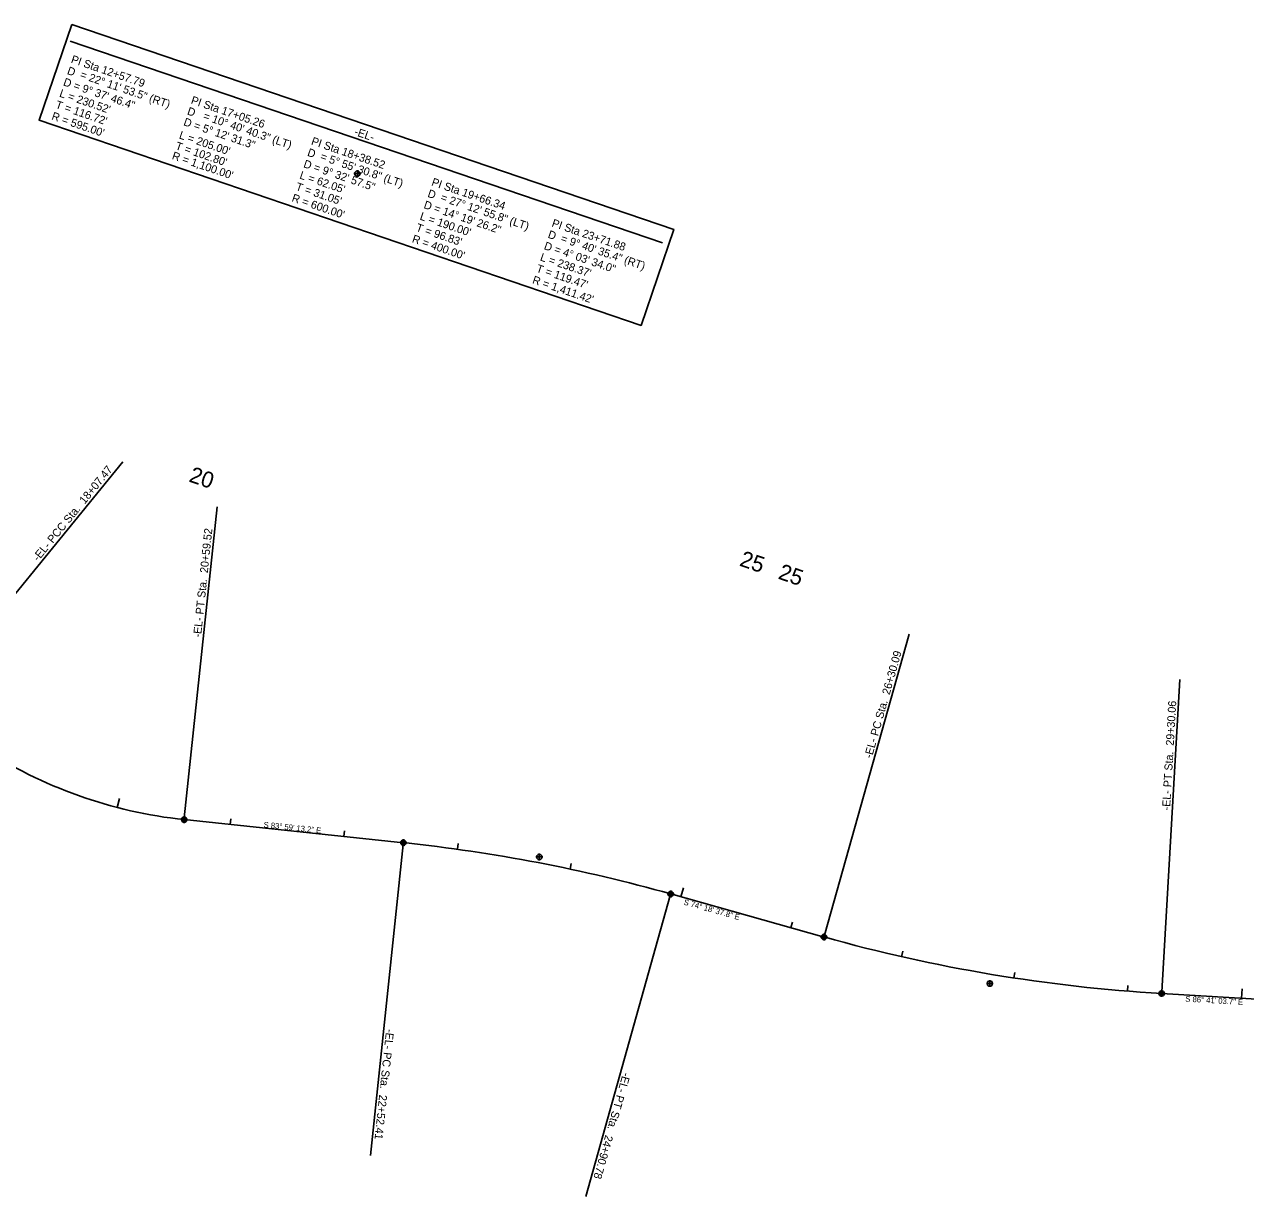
# Model space of a CAD drawing. Extents: x 928071 to 937324, y 684061 to 686812.
# Drawn here: x 928766 to 929834, y 685582 to 686607 of the extents above; entities that cross this region are included whole.
import ezdxf

# ---------------------------------------------------------------- set-up
doc = ezdxf.new("R2010")
doc.units = 0
for name, color, linetype in [('COGO Default Chain', 7, 'Continuous'), ('COGO Default Curve', 7, 'Continuous'), ('Cogo Default Point CELL', 7, 'Continuous'), ('Default', 7, 'Continuous'), ('Exist Horizontal Alignment', 7, 'Continuous'), ('Exist Horizontal Alignment Curve and Spiral Data', 7, 'Continuous'), ('Exist Horizontal Alignment Direction Label', 7, 'Continuous'), ('Exist Horizontal Alignment Station Label', 7, 'Continuous'), ('Exist Horizontal Alignment Tick Label', 7, 'Continuous'), ('Exist Horizontal Alignment Tick Large', 7, 'Continuous'), ('Exist Horizontal Alignment Tick Small', 7, 'Continuous')]:
    doc.layers.add(name, color=color, linetype=linetype)

msp = doc.modelspace()

# ---------------------------------------------------------------- linework, layer by layer
at = {"layer": 'COGO Default Chain'}
for p, q in [((928906, 685911.7), (929097.8, 685891.5)), ((929331.6, 685846.7), (929465.7, 685809)), ((929761, 685759.6), (929854.3, 685754.2))]:
    msp.add_line(p, q, dxfattribs=at)
for centre, radius, start, end in [((928947.9, 686309.5), 400, 236.7715, 263.987), ((928949.9, 684487.9), 1411.4, 74.3105, 83.987), ((929841.4, 687146.3), 1389, 254.3105, 266.6844)]:
    msp.add_arc(centre, radius, start, end, dxfattribs=at)
at = {"layer": 'COGO Default Curve'}
for centre, radius, start, end in [((928947.9, 686309.5), 400, 236.7715, 263.987), ((928949.9, 684487.9), 1411.4, 74.3105, 83.987), ((929841.4, 687146.3), 1389, 254.3105, 266.6844)]:
    msp.add_arc(centre, radius, start, end, dxfattribs=at)
at = {"layer": 'Cogo Default Point CELL'}
for points in [[(929054.5, 686476.8), (929057.5, 686476.8)], [(929057.5, 686479.8), (929057.5, 686476.8)], [(929057.5, 686476.8), (929060.5, 686476.8)], [(929057.5, 686476.8), (929057.5, 686473.8)], [(928903, 685911.7), (928906, 685911.7)], [(928906, 685914.7), (928906, 685911.7)], [(928906, 685911.7), (928909, 685911.7)], [(928906, 685911.7), (928906, 685908.7)], [(929094.8, 685891.5), (929097.8, 685891.5)], [(929097.8, 685894.5), (929097.8, 685891.5)], [(929097.8, 685891.5), (929100.8, 685891.5)], [(929097.8, 685891.5), (929097.8, 685888.5)], [(929213.6, 685879), (929216.6, 685879)], [(929216.6, 685882), (929216.6, 685879)], [(929216.6, 685879), (929219.6, 685879)], [(929216.6, 685879), (929216.6, 685876)], [(929328.6, 685846.7), (929331.6, 685846.7)], [(929331.6, 685849.7), (929331.6, 685846.7)], [(929331.6, 685846.7), (929334.6, 685846.7)], [(929331.6, 685846.7), (929331.6, 685843.7)], [(929462.7, 685809), (929465.7, 685809)], [(929465.7, 685812), (929465.7, 685809)], [(929465.7, 685809), (929468.7, 685809)], [(929465.7, 685809), (929465.7, 685806)], [(929607.7, 685768.3), (929610.7, 685768.3)], [(929610.7, 685771.3), (929610.7, 685768.3)], [(929610.7, 685768.3), (929613.7, 685768.3)], [(929610.7, 685768.3), (929610.7, 685765.3)], [(929761, 685762.6), (929761, 685759.6)], [(929758, 685759.6), (929761, 685759.6)], [(929761, 685759.6), (929764, 685759.6)], [(929761, 685759.6), (929761, 685756.6)]]:
    msp.add_lwpolyline(points, dxfattribs=at)
for centre in [(929057.5, 686476.8), (928906, 685911.7), (929097.8, 685891.5), (929216.6, 685879), (929331.6, 685846.7), (929465.7, 685809), (929610.7, 685768.3), (929761, 685759.6)]:
    msp.add_circle(centre, 2.34, dxfattribs=at)
at = {"layer": 'Default'}
for p, q in [((928906, 685911.7), (929097.8, 685891.5)), ((929465.7, 685809), (929331.6, 685846.7)), ((929854.3, 685754.2), (929761, 685759.6))]:
    msp.add_line(p, q, dxfattribs=at)
msp.add_lwpolyline([(928807.7, 686607.3), (929334.2, 686427.9), (929305.6, 686344), (928779.1, 686523.4)], close=True, dxfattribs=at)
for centre, radius, start, end in [((928947.9, 686309.5), 400, 236.7715, 263.987), ((928949.9, 684487.9), 1411.4, 74.3105, 83.987), ((929841.4, 687146.3), 1389, 254.3105, 266.6844)]:
    msp.add_arc(centre, radius, start, end, dxfattribs=at)
at = {"layer": 'Exist Horizontal Alignment'}
for p, q in [((928906, 685911.7), (929097.8, 685891.5)), ((929331.6, 685846.7), (929465.7, 685809)), ((929761, 685759.6), (929854.3, 685754.2))]:
    msp.add_line(p, q, dxfattribs=at)
for centre, radius, start, end in [((928947.9, 686309.5), 400, 236.7715, 263.987), ((928949.9, 684487.9), 1411.4, 74.3105, 83.987), ((929841.4, 687146.3), 1389, 254.3105, 266.6844)]:
    msp.add_arc(centre, radius, start, end, dxfattribs=at)
at = {"layer": 'Exist Horizontal Alignment Curve and Spiral Data'}
msp.add_line((928806.3, 686592.6), (929324.4, 686416.1), dxfattribs=at)
at = {"layer": 'Exist Horizontal Alignment Station Label'}
for p, q in [((928679.6, 686012.7), (928852.3, 686224.8)), ((928906.1, 685913.2), (928934.8, 686185.2)), ((929466.1, 685810.5), (929540.1, 686073.8)), ((929761.1, 685761.1), (929776.9, 686034.2)), ((929097.6, 685890), (929069, 685618)), ((929331.2, 685845.3), (929257.3, 685582))]:
    msp.add_line(p, q, dxfattribs=at)
for centre in [(928906, 685911.7), (929097.8, 685891.5), (929331.6, 685846.7), (929465.7, 685809), (929761, 685759.6)]:
    msp.add_circle(centre, 1.5, dxfattribs=at)
at = {"layer": 'Exist Horizontal Alignment Tick Large'}
for p, q in [((928847.5, 685922.3), (928849.5, 685930.1)), ((929340.5, 685844.2), (929342.7, 685851.9)), ((929830.8, 685755.6), (929831.3, 685763.6))]:
    msp.add_line(p, q, dxfattribs=at)
at = {"layer": 'Exist Horizontal Alignment Tick Small'}
for p, q in [((928946.2, 685907.5), (928946.7, 685912.5)), ((929045.7, 685897), (929046.2, 685902)), ((929145, 685885.8), (929145.7, 685890.7)), ((929243.5, 685868.4), (929244.5, 685873.3)), ((929436.8, 685817.2), (929438.1, 685822)), ((929533.5, 685791.8), (929534.6, 685796.7)), ((929631.7, 685773.2), (929632.5, 685778.1)), ((929731, 685761.7), (929731.4, 685766.7))]:
    msp.add_line(p, q, dxfattribs=at)

# ---------------------------------------------------------------- texts
at = {"layer": 'Exist Horizontal Alignment Curve and Spiral Data'}
for s, rotation, p in [('PI Sta 12+57.79', 341.0779, (928806.5, 686574)), ('D', 341.0779, (928803.1, 686564)), ('= 22%%d 11\' 53.5" (RT)', 341.0779, (928814.4, 686560.6)), ('D = 9%%d 37\' 46.4"', 341.0779, (928799.7, 686554.1)), ("T = 116.72'", 341.0779, (928792.9, 686534.3)), ("L = 230.52'", 341.0779, (928796.3, 686544.2)), ('PI Sta 17+05.26', 341.1836, (928911.4, 686538.2)), ("R = 595.00'", 341.0779, (928789.5, 686524.3)), ('D', 341.1836, (928908.1, 686528.6)), ('D = 5%%d 12\' 31.3"', 341.1836, (928904.9, 686519.2)), ('= 10%%d 40\' 40.3" (LT)', 341.1836, (928922.1, 686524.4)), ("L = 205.00'", 341.1836, (928901, 686507.7)), ('PI Sta 18+38.52', 341.1836, (929016.6, 686502.4)), ('-EL-', 341.1836, (929054.2, 686510.7)), ("T = 102.80'", 341.1836, (928897.8, 686498.2)), ('D', 341.1836, (929013.2, 686492.5)), ("R = 1,100.00'", 341.1836, (928894.8, 686489.6)), ('D = 9%%d 32\' 57.5"', 341.1836, (929009.8, 686482.5)), ('= 5%%d 55\' 30.8" (LT)', 341.1836, (929024.5, 686489)), ("L = 62.05'", 341.1836, (929006.4, 686472.6)), ("T = 31.05'", 341.1836, (929003, 686462.6)), ('PI Sta 19+66.34', 341.1836, (929121.8, 686466.6)), ("R = 600.00'", 341.1836, (928999.6, 686452.7)), ('D', 341.1836, (929118.4, 686456.6)), ('= 27%%d 12\' 55.8" (LT)', 341.1836, (929129.7, 686453.2)), ('D = 14%%d 19\' 26.2"', 341.1836, (929115, 686446.7)), ("L = 190.00'", 341.1836, (929111.6, 686436.7)), ('PI Sta 23+71.88', 341.1836, (929227, 686430.7)), ("R = 400.00'", 341.1836, (929104.8, 686416.9)), ("T = 96.83'", 341.1836, (929108.2, 686426.8)), ('D', 341.1836, (929223.6, 686420.8)), ('D = 4%%d 03\' 34.0"', 341.1836, (929220.2, 686410.8)), ('= 9%%d 40\' 35.4" (RT)', 341.1836, (929234.8, 686417.3)), ("L = 238.37'", 341.1836, (929216.8, 686400.9)), ("T = 119.47'", 341.1836, (929213.4, 686391)), ("R = 1,411.42'", 341.1836, (929210, 686381))]:
    msp.add_text(s, height=7, rotation=rotation, dxfattribs=at).set_placement(p)
at = {"layer": 'Exist Horizontal Alignment Direction Label'}
for s, rotation, p in [('S 83%%d 59\' 13.2" E', 353.987, (928975.3, 685904.9)), ('S 74%%d 18\' 37.8" E', 344.3105, (929342.5, 685837.4)), ('S 86%%d 41\' 03.7" E', 356.6844, (929781.6, 685752.5))]:
    msp.add_text(s, height=5, rotation=rotation, dxfattribs=at).set_placement(p)
at = {"layer": 'Exist Horizontal Alignment Station Label'}
for s, rotation, p in [('-EL- PCC Sta.  18+07.47', 50.8463, (928778.3, 686137.2)), ('-EL- PT Sta.  20+59.52', 83.987, (928920.7, 686070.7)), ('-EL- PC Sta.  26+30.09', 74.3105, (929507.4, 685964.8)), ('-EL- PT Sta.  29+30.06', 86.6844, (929768.3, 685919.6)), ('-EL- PC Sta.  22+52.41', 263.987, (929082.7, 685728.7)), ('-EL- PT Sta.  24+90.78', 254.3105, (929289.9, 685690.9))]:
    msp.add_text(s, height=7, rotation=rotation, dxfattribs=at).set_placement(p)
at = {"layer": 'Exist Horizontal Alignment Tick Label'}
for s, p in [('20', (928909.4, 686207.6)), ('25', (929391, 686134)), ('25', (929424.8, 686122.6))]:
    msp.add_text(s, height=14, rotation=341.1836, dxfattribs=at).set_placement(p)

doc.saveas('drawing.dxf')
